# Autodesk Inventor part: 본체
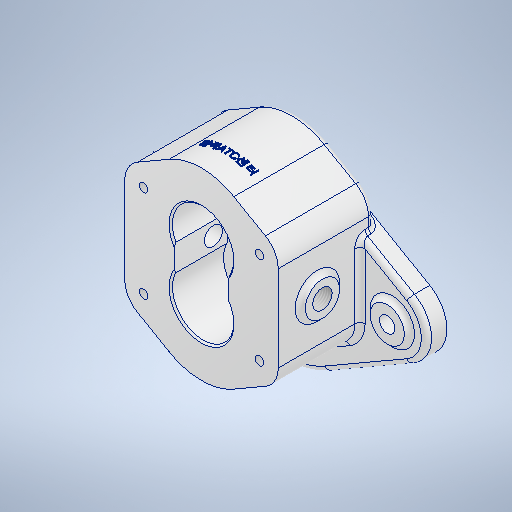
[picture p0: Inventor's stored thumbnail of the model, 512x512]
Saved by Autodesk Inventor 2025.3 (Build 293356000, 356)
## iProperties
Created: 2025-11
Part Number: 본체
Material: 알루미늄 6061
Document SubType Name: Modeling
Designer: PC-04
Density: 2.7 g/cm^3
Appearance: 알루미늄 - 평지
Mass: 1252.33 g
Surface Area: 588.016 cm^2
Volume: 463.826 cm^3
Author: PC-04
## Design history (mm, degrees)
sketch "스케치1"
  geometry: L1 (-45, 54)-(45, 54); L2 (45, 54)-(45, -54); L3 (45, -54)-(-45, -54); L4 (-45, -54)-(-45, 54); L5 (-45, 54)-(45, -54); L6 (45, 54)-(-45, -54); L7 (45, -33.898)-(19, -48.909); L8 (19, 48.909)-(45, 33.898); L9 (-45, 0)-(45, 0); L10 (0, 54)-(0, -54); L11 (-19, 48.909)-(-45, 33.898); L12 (-45, -33.898)-(-19, -48.909); A1 r 38 centre (0, -16) between (19, -48.909) and (0, -54); A2 r 38 centre (0, 16) between (19, 48.909) and (0, 54); 7 further points
  constraints: 24 end point, 6 midpoint, 4 point on circle, 4 symmetric about line, 2 centre point, 2 coincident, 2 parallel, 2 point on line, 2 tangent, 1 horizontal, 1 perpendicular
  dimensions: "d0" = 90 distance of L2.end L3.end; "d1" = 108 distance of L1.end L2.end; "d2" = 16 distance of point (0, 0) point (0, 16); "d3" = 16 distance of point (0, 0) point (0, -16); "d4" = 45 distance from line of L2 point (0, 16); "d5" = 45 distance from line of L2 point (0, -16); "d6" = 76 diameter of A1; "d7" = 76 diameter of A2; "d8" = 30 deg angle of L9 L8; "d9" = 30 deg angle of L9 L7
extrude "돌출1" new body sketch "스케치1" stored distance "d10" = 56; taper "d11" = 0 deg
fillet "모깎기1" dims "d12" = 15
sketch "스케치2"
  geometry: L1 (54, -28)-(-54, -28) reference; L2 (-54, -28)-(-54, 28) reference; L3 (-54, 28)-(54, 28) reference; L4 (54, 28)-(54, -28) reference; L5 (16, 28)-(16, -28); L6 (34, 27)-(34, -3); L7 (25.238, -28)-(25.238, 28) reference; L8 (34, -3)-(28.5, -3); L9 (27.5, -4)-(27.5, -18); L10 (27.5, -18)-(16, -18); L11 (35, 28)-(54, 28); L12 (35, 28)-(34, 27); L13 (28.5, -3)-(27.5, -4); 5 further points
  constraints: 16 end point, 8 point on line, 4 perpendicular, 1 collinear, 1 parallel
  dimensions: "d13" = 16 distance from line of point (0, 0) L5; "d14" = 15 distance between parallel lines of L8 L10; "d15" = 31 distance between parallel lines of L3 L8; "d16" = 36 diameter of L6 L5; "d17" = 23 diameter of L9 L5; "d18" = 1 distance of L11.start point (34, 28); "d19" = 1 distance of L6.start point (34, 28) (= d18); "d20" = 1 distance of L8.end point (27.5, -3) (= d18); "d21" = 1 distance of L9.start point (27.5, -3) (= d20)
revolve "회전1" sketch "스케치2" stored, may be unused: angle "d22" = 360 deg
sketch "스케치3"
  geometry: L1 (25.238, 28)-(-25.238, 28) reference; L2 (-16, 28)-(-16, -28); L3 (-25.238, -28)-(25.238, -28) reference; L4 (54, -28)-(-54, -28) reference; L5 (-54, -28)-(-54, 28) reference; L6 (-54, 28)-(-3, 28) reference; L7 (-3, 28)-(-2, 27) reference; L8 (-2, 27)-(-2, -3) reference; L9 (-2, -3)-(3.5, -3) reference; L10 (3.5, -3)-(4.5, -4) reference; L11 (4.5, -4)-(4.5, -18) reference; L12 (4.5, -18)-(27.5, -18) reference; L13 (27.5, -18)-(27.5, -4) reference; L14 (27.5, -4)-(28.5, -3) reference; L15 (28.5, -3)-(34, -3) reference; L16 (34, -3)-(34, 27) reference; L17 (34, 27)-(35, 28) reference; L18 (35, 28)-(54, 28) reference; L19 (54, 28)-(54, -28) reference; L20 (0, 28)-(0, -28); L21 (-35, 28)-(-54, 28); L22 (-34, 27)-(-35, 28); L23 (-34, -3)-(-34, 27); L24 (-28.5, -3)-(-34, -3); L25 (-27.5, -4)-(-28.5, -3); L26 (-27.5, -18)-(-27.5, -4); L27 (-4.5, -18)-(-27.5, -18); 3 further points
  constraints: 18 end point, 7 symmetric about line, 2 midpoint, 2 point on line, 1 vertical
  dimensions: "d23" = 16 distance from line of L2 point (0, 0)
revolve "회전2" sketch "스케치3" stored, may be unused: angle "d24" = 90 deg
sketch "스케치4"
  geometry: L1 (-16, 16)-(16, 16); L2 (16, 16)-(16, -16); L3 (16, -16)-(-16, -16); L4 (-16, -16)-(-16, 16); L5 (-16, 16)-(16, -16); L6 (16, 16)-(-16, -16); 1 further point
  constraints: 12 end point, 2 midpoint, 2 parallel, 1 horizontal, 1 perpendicular
  dimensions: "d25" = 32 distance of L2.end L3.end; "d26" = 32 distance of L1.end L2.end
extrude "돌출2" cut sketch "스케치4" distance "d27" = 31; taper "d28" = 0 deg
node "작업 평면1"
sketch "스케치5"
  geometry: L1 (-74, 1.321)-(-26, 29.033); L2 (-74, -33.321)-(-26, -61.033); L3 (26, -61.033)-(74, -33.321); L4 (74, 1.321)-(26, 29.033); C1 r 11.5 at (0, -16) reference; A1 r 52 centre (0, -16) between (-26, 29.033) and (-26, -61.033); A2 r 20 centre (-64, -16) between (-74, 1.321) and (-74, -33.321); A3 r 20 centre (64, -16) between (74, -33.321) and (74, 1.321); 2 further points
  constraints: 8 end point, 8 point on circle, 8 tangent, 3 centre point, 2 coincident, 2 horizontal alignment
  dimensions: "d32" = 104 diameter of A1; "d33" = 40 diameter of A2; "d34" = 40 diameter of A3; "d35" = 64 distance of point (0, -16) A3.centre; "d36" = 128 distance of A2.centre A3.centre
extrude "돌출3" join sketch "스케치5" distance "d37" = 12; taper "d38" = 0 deg
sketch "스케치7"
  geometry: C1 r 11.5 at (0, -16) reference; C2 r 25 at (0, -16); 1 further point
  constraints: 1 centre point, 1 coincident
  dimensions: "d46" = 50 diameter of C2
extrude "돌출4" join sketch "스케치7" distance "d47" = 4; taper "d48" = 0 deg
sketch "스케치8"
  geometry: L1 (-4.5, -18)-(-27.5, -18) reference; L2 (-16, -18)-(-16, -36); L3 (-41, -36)-(9, -36) reference; L4 (-5.5, -18)-(-5.5, -28.7); L5 (-5.5, -28.7)-(-1.3, -28.7); L6 (-1, -29)-(-1, -35.3); L7 (-0.596, -36)-(9, -36); L8 (-1, -35.3)-(-0.596, -36); A1 r 0.3 centre (-1.3, -29) between (-1, -29) and (-1.3, -28.7); 3 further points
  constraints: 12 end point, 4 point on line, 2 midpoint, 2 perpendicular, 2 point on circle, 2 tangent, 1 centre point, 1 collinear, 1 vertical
  dimensions: "d49" = 30 diameter of L6 L2; "d50" = 21 diameter of L4 L2; "d51" = 7.3 distance between parallel lines of L3 L5; "d52" = 0.3 radius of A1 (derived); "d53" = 0.7 distance of L6.end point (-1, -36); "d54" = 30 deg angle of L6 L8
revolve "회전4" sketch "스케치8" stored, may be unused: angle "d55" = 90 deg
sketch "스케치9"
  geometry: 1 further point
chamfer "모따기1" distance "d56" = 1; stored, may be unused: second distance "d57" = 2, angle "d58" = 45 deg
sketch "스케치12"
  geometry: C1 r 10 at (64, -16); A1 r 20 centre (64, -16) between (74, -33.321) and (74, 1.321) reference; 1 further point
  constraints: 1 centre point, 1 coincident
  dimensions: "d74" = 20 diameter of C1
extrude "돌출6" join sketch "스케치12" distance "d75" = 3; taper "d76" = 0 deg
sketch "스케치13"
  geometry: L1 (-19, -9.238)-(-19, 41.238) reference; 2 further points
  dimensions: "d77" = 16 vertical distance of point (-64, 16) point (0, 0); "d78" = 19 distance from line of L1 point (0, 0)
hole "구멍2" sketch "스케치13" at (0, 0) diameter "d79" = 9; stored, may be unused: countersink angle "d83" = 90 deg, drill point angle "d85" = 0 deg; dims "d80" = 11, "d81" = 4, "d82" = 2, "d84" = 8
sketch "스케치14"
  geometry: L1 (-34, 27)-(34, 27); L2 (34, 27)-(34, -27); L3 (34, -27)-(-34, -27); L4 (-34, -27)-(-34, 27); L5 (-34, 27)-(34, -27); L6 (34, 27)-(-34, -27); 5 further points
  constraints: 12 end point, 4 coincident, 2 midpoint, 2 parallel, 1 horizontal, 1 perpendicular
  dimensions: "d86" = 68 distance of L2.end L3.end; "d87" = 54 distance of L1.end L2.end
hole "구멍3" sketch "스케치14" at (-34, 27), (34, 27), (34, -27), (-34, -27) diameter "d88" = 4.917; stored, may be unused: countersink angle "d92" = 90 deg, drill point angle "d94" = 118 deg; dims "d89" = 12, "d90" = 4, "d91" = 2, "d93" = 14
fillet "모깎기2" dims "d95" = 3
fillet "모깎기4" dims "d97" = 3
fillet "모깎기5" dims "d98" = 3
fillet "모깎기6" dims "d99" = 3
sketch "스케치15"
  geometry: L1 (-45, 28)-(-37.5, 28) reference; 2 further points
  constraints: 1 vertical alignment, 1 other
  dimensions: "d100" = 16 distance from line of L1 point (0, 12)
feature "엠보싱1" sketch "스케치15" dims "d0" = 90, "d1" = 108, "d2" = 16, "d3" = 16, "d4" = 45, "d5" = 45, "d6" = 76, "d7" = 76, "d8" = 30 deg, "d9" = 30 deg, "d101" = 0.5, "d102" = 0
sketch "스케치18"
  geometry: L1 (0, 0)-(0, 50.475) reference; L2 (0, 25.238)-(28, 25.238); C1 r 10 at (23, 25.228); 1 further point
  constraints: 2 end point, 1 centre point, 1 coincident, 1 horizontal, 1 midpoint
  dimensions: "d119" = 23 distance from line of L1 point (23, 25.228); "d120" = 0.01 distance from line of L2 point (23, 25.228); "d121" = 20 diameter of C1
extrude "돌출8" join sketch "스케치18" distance "d122" = 3; taper "d123" = 0 deg
sketch "스케치19"
  geometry: L1 (-23, -25.228)-(-23, 25.248) reference; L2 (-23, 25.248)-(30, 25.248) reference; 2 further points
  dimensions: "d124" = 23 distance from line of L1 point (0, 0); "d125" = 25.2476 distance from line of L2 point (0, 0)
hole "구멍5" sketch "스케치19" at (0, 0) diameter "d126" = 10.5; stored, may be unused: countersink angle "d132" = 90 deg, drill point angle "d134" = 0 deg; dims "d127" = 11, "d128" = 0.62479, "d129" = 10.589, "d130" = 4, "d131" = 2, "d133" = 32
fillet "모깎기7" dims "d135" = 3
node "솔리드1"
mirror "미러1"
mirror "미러2"
mirror "미러4"
node "작업 평면2"
node "절단 모서리 투영1"
node "절단 모서리 투영2"
feature "A9D066F2-1C7D-4E18-AEED-F7BC21143FA4" dims "d79" = 9, "d80" = 11, "d81" = 4, "d82" = 2, "d83" = 90 deg, "d84" = 8, "d85" = 0
